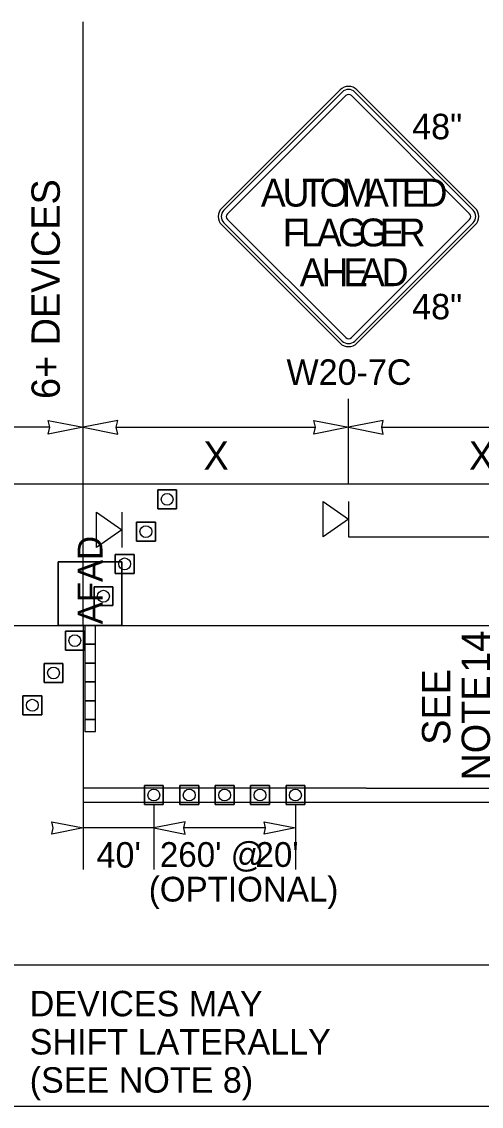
# Model space of a CAD drawing. Extents: x 99999.1 to 100095.7, y 99995 to 100010.7.
# Drawn here: x 100051.3 to 100052.598, y 100005.732 to 100008.799 of the extents above; entities that cross this region are included whole.
import ezdxf

# ---------------------------------------------------------------- set-up
doc = ezdxf.new("R2010")
doc.units = 0
for name, color, linetype in [('RD_ED_ShoulderPavedEdge', 7, 'Continuous'), ('RD_MK_LineDblYellowCenter', 7, 'Continuous'), ('RD_MK_LineEdgeWhite', 7, 'Continuous'), ('RD_MK_LineNoPass', 7, 'Continuous'), ('RD_MK_LineSkipCenter', 7, 'Continuous'), ('TR_SN_ConstructionSigns', 7, 'Continuous'), ('TR_WZ_AFAD', 7, 'Continuous'), ('TR_WZ_PortableSignMountBlk-Org', 7, 'Continuous'), ('TR_WZ_PortableSignMountBlk-Wht', 7, 'Continuous'), ('TR_WZ_TrafficCone', 7, 'Continuous'), ('TR_WZ_WorkZoneDetails', 7, 'Continuous'), ('TR_WZ_WorkZoneTextCurrent', 7, 'Continuous')]:
    doc.layers.add(name, color=color, linetype=linetype)

msp = doc.modelspace()

# ---------------------------------------------------------------- linework, layer by layer
at = {"layer": 'RD_ED_ShoulderPavedEdge'}
for p, q in [((100040.1076, 100007.4923), (100055.6424, 100007.4923)), ((100040.1076, 100005.7323), (100055.6424, 100005.7323))]:
    msp.add_line(p, q, dxfattribs=at)
at = {"layer": 'RD_MK_LineDblYellowCenter'}
for p, q in [((100052.2733, 100006.6323), (100055.6631, 100006.6323)), ((100052.2733, 100006.5923), (100055.6218, 100006.5923))]:
    msp.add_line(p, q, dxfattribs=at)
at = {"layer": 'RD_MK_LineEdgeWhite'}
for p, q in [((100040.1076, 100007.0923), (100055.6424, 100007.0923)), ((100040.1076, 100006.1323), (100055.6424, 100006.1323))]:
    msp.add_line(p, q, dxfattribs=at)
at = {"layer": 'RD_MK_LineNoPass'}
msp.add_line((100051.4733, 100006.5923), (100052.2733, 100006.5923), dxfattribs=at)
at = {"layer": 'RD_MK_LineSkipCenter'}
msp.add_lwpolyline([(100052.2733, 100006.6323), (100051.4733, 100006.6323)], dxfattribs=at)
at = {"layer": 'TR_SN_ConstructionSigns'}
for p, q in [((100052.1995, 100008.6062), (100051.8654, 100008.2721)), ((100052.5813, 100008.2721), (100052.2472, 100008.6062)), ((100052.2055, 100008.6002), (100051.8713, 100008.2661)), ((100051.8813, 100008.2561), (100052.2154, 100008.5903)), ((100052.2313, 100008.5903), (100052.5654, 100008.2561)), ((100052.5754, 100008.2661), (100052.2412, 100008.6002)), ((100052.2154, 100007.9061), (100051.8813, 100008.2402)), ((100052.5654, 100008.2402), (100052.2313, 100007.9061)), ((100051.8654, 100008.2243), (100052.1995, 100007.8902)), ((100051.8713, 100008.2303), (100052.2055, 100007.8962)), ((100052.2412, 100007.8962), (100052.5754, 100008.2303)), ((100052.2472, 100007.8902), (100052.5813, 100008.2243))]:
    msp.add_line(p, q, dxfattribs=at)
for centre, radius, start, end in [((100052.2233, 100008.5823), 0.0338, 45, 135), ((100052.2233, 100008.5823), 0.0253, 45, 135), ((100052.2233, 100008.5823), 0.0113, 45, 135), ((100051.8892, 100008.2482), 0.0338, 135, 225), ((100051.8892, 100008.2482), 0.0253, 135, 225), ((100052.5575, 100008.2482), 0.0253, 315, 45), ((100052.5575, 100008.2482), 0.0338, 315, 45), ((100051.8892, 100008.2482), 0.0113, 135, 225), ((100052.5575, 100008.2482), 0.0113, 315, 45), ((100052.2233, 100007.9141), 0.0113, 225, 315), ((100052.2233, 100007.9141), 0.0338, 225, 315), ((100052.2233, 100007.9141), 0.0253, 225, 315)]:
    msp.add_arc(centre, radius, start, end, dxfattribs=at)
at = {"layer": 'TR_WZ_AFAD'}
for p, q in [((100051.4033, 100007.0923), (100051.4033, 100007.2723)), ((100051.4033, 100007.2723), (100051.5833, 100007.2723)), ((100051.5833, 100007.2723), (100051.4033, 100007.2723)), ((100051.4033, 100007.2723), (100051.4033, 100007.0923)), ((100051.5833, 100007.2723), (100051.5833, 100007.0923)), ((100051.5833, 100007.0923), (100051.5833, 100007.2723)), ((100051.5833, 100007.0923), (100051.4033, 100007.0923)), ((100051.5, 100007.0923), (100051.4933, 100007.0923)), ((100051.5, 100007.0923), (100051.5833, 100007.0923)), ((100051.5083, 100007.0923), (100051.5, 100007.0923)), ((100051.5083, 100007.039), (100051.5083, 100007.0923)), ((100051.4783, 100007.039), (100051.4783, 100006.9857)), ((100051.5083, 100006.9857), (100051.5083, 100007.039)), ((100051.4783, 100006.9857), (100051.4783, 100006.9323)), ((100051.4783, 100006.9857), (100051.4933, 100006.9857)), ((100051.4933, 100006.9857), (100051.5083, 100006.9857)), ((100051.5083, 100006.9323), (100051.5083, 100006.9857)), ((100051.4933, 100006.9323), (100051.4783, 100006.9323)), ((100051.4783, 100006.9323), (100051.4783, 100006.879)), ((100051.5083, 100006.9323), (100051.4933, 100006.9323)), ((100051.5083, 100006.879), (100051.5083, 100006.9323)), ((100051.4783, 100006.879), (100051.4783, 100006.8257)), ((100051.4783, 100006.879), (100051.4933, 100006.879)), ((100051.4933, 100006.879), (100051.5083, 100006.879)), ((100051.5083, 100006.8257), (100051.5083, 100006.879)), ((100051.4933, 100006.8257), (100051.4783, 100006.8257)), ((100051.4783, 100006.8257), (100051.4783, 100006.7923)), ((100051.5083, 100006.8257), (100051.4933, 100006.8257))]:
    msp.add_line(p, q, dxfattribs=at)
for points in [[(100051.4033, 100007.0923), (100051.4867, 100007.0923), (100051.5, 100007.0923)], [(100051.4933, 100007.0923), (100051.4867, 100007.0923), (100051.4783, 100007.0923), (100051.4783, 100007.039)], [(100051.4783, 100007.0923), (100051.4783, 100006.7923), (100051.5083, 100006.7923), (100051.5083, 100007.0923)], [(100051.4783, 100007.039), (100051.4933, 100007.039), (100051.5083, 100007.039)], [(100051.5083, 100007.039), (100051.4933, 100007.039), (100051.4783, 100007.039)], [(100051.5083, 100006.9857), (100051.4933, 100006.9857), (100051.4783, 100006.9857)], [(100051.4783, 100006.9323), (100051.4933, 100006.9323), (100051.5083, 100006.9323)], [(100051.5083, 100006.879), (100051.4933, 100006.879), (100051.4783, 100006.879)], [(100051.4783, 100006.8257), (100051.4933, 100006.8257), (100051.5083, 100006.8257)], [(100051.4783, 100006.7923), (100051.5083, 100006.7923), (100051.5083, 100006.8257)]]:
    msp.add_lwpolyline(points, dxfattribs=at)
at = {"layer": 'TR_WZ_PortableSignMountBlk-Org'}
msp.add_line((100052.2233, 100007.4422), (100052.2233, 100007.3422), dxfattribs=at)
msp.add_lwpolyline([(100052.2233, 100007.3923), (100052.1515, 100007.3422), (100052.1515, 100007.4422)], close=True, dxfattribs=at)
at = {"layer": 'TR_WZ_PortableSignMountBlk-Wht'}
msp.add_line((100051.5833, 100007.4123), (100051.5833, 100007.3123), dxfattribs=at)
msp.add_lwpolyline([(100051.5833, 100007.3624), (100051.5115, 100007.3123), (100051.5115, 100007.4123)], close=True, dxfattribs=at)
at = {"layer": 'TR_WZ_TrafficCone'}
for points in [[(100051.6843, 100007.4753), (100051.7376, 100007.4753), (100051.7376, 100007.422), (100051.6843, 100007.422), (100051.6843, 100007.4753)], [(100051.6843, 100007.422), (100051.7376, 100007.422), (100051.7376, 100007.4753), (100051.6843, 100007.4753), (100051.6843, 100007.422)], [(100051.6243, 100007.384), (100051.6776, 100007.384), (100051.6776, 100007.3306), (100051.6243, 100007.3306), (100051.6243, 100007.384)], [(100051.6243, 100007.3306), (100051.6776, 100007.3306), (100051.6776, 100007.384), (100051.6243, 100007.384), (100051.6243, 100007.3306)], [(100051.5643, 100007.2926), (100051.6176, 100007.2926), (100051.6176, 100007.2393), (100051.5643, 100007.2393), (100051.5643, 100007.2926)], [(100051.5643, 100007.2393), (100051.6176, 100007.2393), (100051.6176, 100007.2926), (100051.5643, 100007.2926), (100051.5643, 100007.2393)], [(100051.5043, 100007.2013), (100051.5576, 100007.2013), (100051.5576, 100007.148), (100051.5043, 100007.148), (100051.5043, 100007.2013)], [(100051.5043, 100007.148), (100051.5576, 100007.148), (100051.5576, 100007.2013), (100051.5043, 100007.2013), (100051.5043, 100007.148)], [(100051.4766, 100007.0757), (100051.4233, 100007.0757), (100051.4233, 100007.0224), (100051.4766, 100007.0224), (100051.4766, 100007.0757)], [(100051.4766, 100007.0224), (100051.4233, 100007.0224), (100051.4233, 100007.0757), (100051.4766, 100007.0757), (100051.4766, 100007.0224)], [(100051.4166, 100006.9844), (100051.3633, 100006.9844), (100051.3633, 100006.9311), (100051.4166, 100006.9311), (100051.4166, 100006.9844)], [(100051.4166, 100006.9311), (100051.3633, 100006.9311), (100051.3633, 100006.9844), (100051.4166, 100006.9844), (100051.4166, 100006.9311)], [(100051.3566, 100006.8931), (100051.3033, 100006.8931), (100051.3033, 100006.8397), (100051.3566, 100006.8397), (100051.3566, 100006.8931)], [(100051.3566, 100006.8397), (100051.3033, 100006.8397), (100051.3033, 100006.8931), (100051.3566, 100006.8931), (100051.3566, 100006.8397)], [(100051.7, 100006.639), (100051.6467, 100006.639), (100051.6467, 100006.5857), (100051.7, 100006.5857), (100051.7, 100006.639)], [(100051.7, 100006.5857), (100051.6467, 100006.5857), (100051.6467, 100006.639), (100051.7, 100006.639), (100051.7, 100006.5857)], [(100051.8, 100006.639), (100051.7467, 100006.639), (100051.7467, 100006.5857), (100051.8, 100006.5857), (100051.8, 100006.639)], [(100051.8, 100006.5857), (100051.7467, 100006.5857), (100051.7467, 100006.639), (100051.8, 100006.639), (100051.8, 100006.5857)], [(100051.9, 100006.639), (100051.8467, 100006.639), (100051.8467, 100006.5857), (100051.9, 100006.5857), (100051.9, 100006.639)], [(100051.9, 100006.5857), (100051.8467, 100006.5857), (100051.8467, 100006.639), (100051.9, 100006.639), (100051.9, 100006.5857)], [(100052, 100006.639), (100051.9467, 100006.639), (100051.9467, 100006.5857), (100052, 100006.5857), (100052, 100006.639)], [(100052, 100006.5857), (100051.9467, 100006.5857), (100051.9467, 100006.639), (100052, 100006.639), (100052, 100006.5857)], [(100052.1, 100006.639), (100052.0467, 100006.639), (100052.0467, 100006.5857), (100052.1, 100006.5857), (100052.1, 100006.639)], [(100052.1, 100006.5857), (100052.0467, 100006.5857), (100052.0467, 100006.639), (100052.1, 100006.639), (100052.1, 100006.5857)]]:
    msp.add_lwpolyline(points, dxfattribs=at)
for centre in [(100051.7109, 100007.4486), (100051.6509, 100007.3573), (100051.5909, 100007.266), (100051.5309, 100007.1746), (100051.45, 100007.0491), (100051.39, 100006.9577), (100051.33, 100006.8664), (100051.6733, 100006.6123), (100051.7733, 100006.6123), (100051.8733, 100006.6123), (100051.9733, 100006.6123), (100052.0733, 100006.6123)]:
    msp.add_circle(centre, 0.0167, dxfattribs=at)
at = {"layer": 'TR_WZ_WorkZoneDetails'}
for p, q in [((100051.4733, 100007.0923), (100051.4733, 100008.7991)), ((100052.2233, 100007.4923), (100052.2233, 100007.7323)), ((100051.3796, 100007.6523), (100051.2437, 100007.6523)), ((100051.5671, 100007.6523), (100052.1296, 100007.6523)), ((100052.3171, 100007.6523), (100052.8796, 100007.6523)), ((100052.2233, 100007.3422), (100055.2233, 100007.3422)), ((100051.4733, 100007.0923), (100051.4733, 100006.4023)), ((100051.6733, 100006.5857), (100051.6733, 100006.4023)), ((100052.0733, 100006.5857), (100052.0733, 100006.4023)), ((100051.6733, 100006.5193), (100051.4733, 100006.5193)), ((100051.989, 100006.5193), (100051.7577, 100006.5193))]:
    msp.add_line(p, q, dxfattribs=at)
for points in [[(100051.4733, 100007.6523), (100051.3751, 100007.6331), (100051.3796, 100007.6523), (100051.3751, 100007.6716)], [(100051.4733, 100007.6523), (100051.5716, 100007.6331), (100051.5671, 100007.6523), (100051.5716, 100007.6716)], [(100052.2233, 100007.6523), (100052.1251, 100007.6331), (100052.1296, 100007.6523), (100052.1251, 100007.6716)], [(100052.2233, 100007.6523), (100052.3216, 100007.6331), (100052.3171, 100007.6523), (100052.3216, 100007.6716)], [(100051.4733, 100006.5193), (100051.3849, 100006.502), (100051.389, 100006.5193), (100051.3849, 100006.5367)], [(100051.6733, 100006.5193), (100051.7618, 100006.502), (100051.7577, 100006.5193), (100051.7618, 100006.5367)], [(100052.0733, 100006.5193), (100051.9849, 100006.502), (100051.989, 100006.5193), (100051.9849, 100006.5367)]]:
    msp.add_lwpolyline(points, close=True, dxfattribs=at)

# ---------------------------------------------------------------- texts
at = {"layer": 'TR_SN_ConstructionSigns'}
for s, p in [('48"', (100052.4031, 100008.4667)), ('48"', (100052.4031, 100007.9576)), ('W20-7C', (100052.0481, 100007.7723))]:
    msp.add_text(s, height=0.072, rotation=360, dxfattribs=at).set_placement(p)
for s, p in [('A', (100051.9757, 100008.2763)), ('U', (100052.0371, 100008.2763)), ('T', (100052.0922, 100008.2763)), ('O', (100052.1418, 100008.2763)), ('M', (100052.2041, 100008.2763)), ('A', (100052.2671, 100008.2763)), ('T', (100052.3222, 100008.2763)), ('E', (100052.3734, 100008.2763)), ('D', (100052.4269, 100008.2763)), ('F', (100052.0375, 100008.1638)), ('L', (100052.0887, 100008.1638)), ('A', (100052.1336, 100008.1638)), ('G', (100052.1934, 100008.1638)), ('G', (100052.2517, 100008.1638)), ('E', (100052.3115, 100008.1638)), ('R', (100052.3651, 100008.1638)), ('A', (100052.0855, 100008.0513)), ('H', (100052.147, 100008.0513)), ('E', (100052.2084, 100008.0513)), ('A', (100052.2556, 100008.0513)), ('D', (100052.3171, 100008.0513))]:
    msp.add_text(s, height=0.0787, dxfattribs=at).set_placement(p)
at = {"layer": 'TR_WZ_AFAD'}
msp.add_text('AFAD', height=0.07, rotation=90, dxfattribs=at).set_placement((100051.5283, 100007.0953))
at = {"layer": 'TR_WZ_WorkZoneDetails'}
for s, p in [('14', (100052.6228, 100006.9581)), ('SEE', (100052.5108, 100006.7544)), ('NOTE', (100052.6228, 100006.6533))]:
    msp.add_text(s, height=0.08, rotation=90, dxfattribs=at).set_placement(p)
at = {"layer": 'TR_WZ_WorkZoneTextCurrent'}
msp.add_text('6+ DEVICES', height=0.08, rotation=90, dxfattribs=at).set_placement((100051.4077, 100007.7323))
for s, height, p in [('X', 0.08, (100051.8136, 100007.5323)), ('X', 0.08, (100052.5636, 100007.5323)), ("40'", 0.072, (100051.5114, 100006.4073)), ("260' @", 0.07, (100051.6903, 100006.4093)), ("20'", 0.07, (100051.9604, 100006.4093)), ('(OPTIONAL)', 0.07, (100051.659, 100006.3113)), ('DEVICES MAY', 0.072, (100051.3226, 100005.9868)), ('SHIFT LATERALLY', 0.072, (100051.3226, 100005.8788)), ('(SEE NOTE 8)', 0.072, (100051.3226, 100005.7708))]:
    msp.add_text(s, height=height, dxfattribs=at).set_placement(p)

doc.saveas('drawing.dxf')
